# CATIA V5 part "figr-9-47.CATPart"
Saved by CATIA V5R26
Part number: Part1
Bounding box of the stored display mesh (mm): x -229.955 to 192.37, y -118.044 to 79.893, z 0 to 72.429
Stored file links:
  D:\_Deepak\CATIA\CATIA V5-6R2016_Deepak\Resources\Part files\Partfiles\c09_catia_v5_6r2016_prt\figr-9-47.CATPart
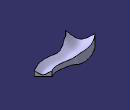
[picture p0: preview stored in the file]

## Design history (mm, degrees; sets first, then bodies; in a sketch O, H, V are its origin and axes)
Body1 (main body)
  Plane1: type Offset, RefPlane yz-plane, Offset 100
  Plane2: type Offset, RefPlane yz-plane, Offset 100, reversed
  Sketch1 on Plane1, origin (100, 0, 0), H (0, 1, 0), V (0, 0, 1)
    point P1 (0, 15.965)
    hyperbola C1
    point P2 (0, 3.0416)
    line L1 (54.8261, 44.8858) -> (54.8261, 0)
    point P5 (54.8261, 0)
    line L2 (-54.8261, 44.8858) -> (-54.8261, 0)
    point P6 (-54.8261, 0)
    line L3 (-54.8261, 0) -> (54.8261, 0)
    coincidence: P1 V, P2 V, P5 H, P6 H
    vertical: L1 V, L2 V
    horizontal: L3 H
  Sketch2 on xy-plane, origin (0, 0, 0), H (1, 0, 0), V (0, 1, 0)
    spline S1 through (-159.6608, -77.1468) (-77.8466, -31.8169) (23.6283, -41.4968) (182.6271, -11.7333)
  Sketch3 on yz-plane, origin (0, 0, 0), H (0, 1, 0), V (0, 0, 1)
    point P1 (0, 18.9787)
    hyperbola C1
    point P2 (0, 2.6681)
    line L1 (48.2237, 37.1764) -> (48.2237, 0)
    point P5 (48.2237, 0)
    line L2 (-43.6563, 34.1546) -> (-43.6563, 0)
    point P6 (-43.6563, 0)
    line L3 (-43.6563, 0) -> (48.2237, 0)
    coincidence: P1 V, P2 V, P5 H, P6 H
    vertical: L1 V, L2 V
    horizontal: L3 H
  Sketch4 on Plane2, origin (-100, 0, 0), H (0, 1, 0), V (0, 0, 1)
    point P1 (0, 140.6052)
    point P2 (0, 41.8972)
    hyperbola C1
    line L1 (78.0478, 72.4293) -> (78.0478, 0)
    point P5 (78.0478, 0)
    line L2 (-78.0478, 72.4293) -> (-78.0478, 0)
    point P6 (-78.0478, 0)
    line L3 (-78.0478, 0) -> (78.0478, 0)
    coincidence: P1 V, P2 V, P5 H, P6 H
    vertical: L1 V, L2 V
    horizontal: L3 H
  Loft1: solid, Sections (Sketch3; Sketch4), Spine Sketch2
